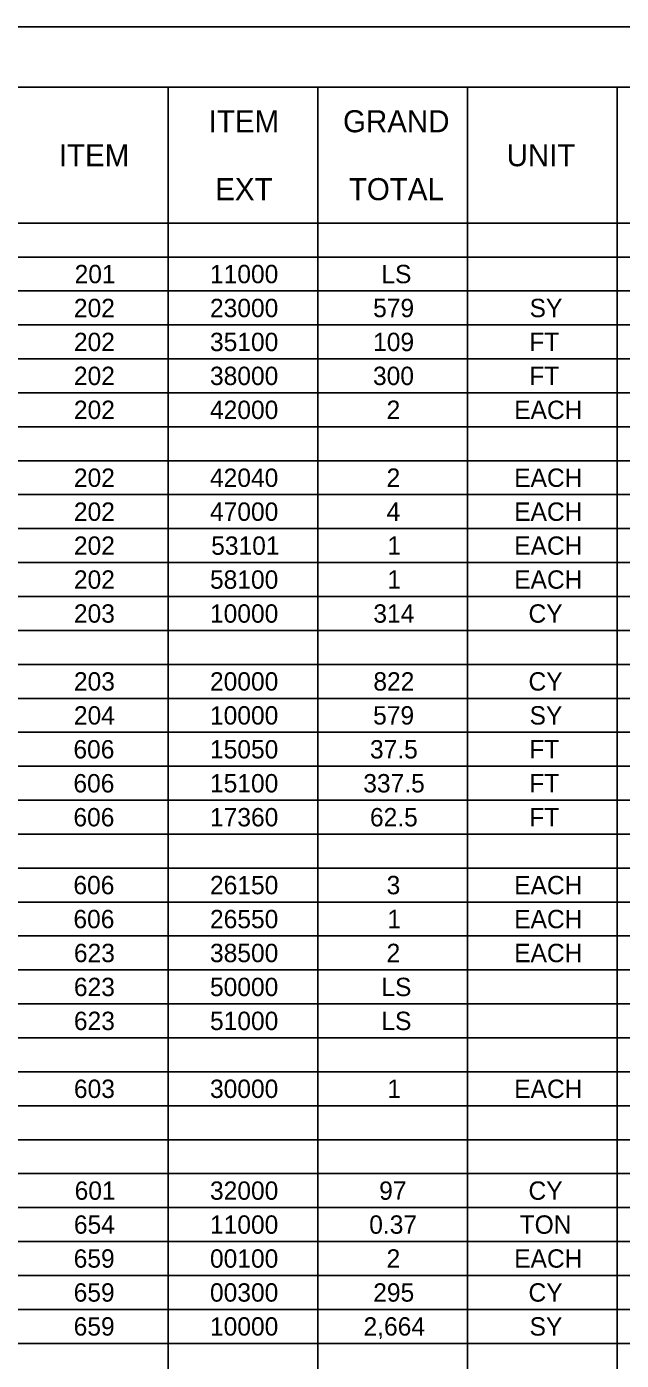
# Model space of a CAD drawing. Extents: x 0 to 34, y 0 to 22.
# Drawn here: x 9.6 to 14.5, y 11 to 22 of the extents above; entities that cross this region are included whole.
import ezdxf

# ---------------------------------------------------------------- set-up
doc = ezdxf.new("R2010")
doc.units = 0
for name, color, linetype in [('Default', 7, 'Continuous'), ('SH_Border', 7, 'Continuous'), ('SH_Cut_Line', 7, 'Continuous')]:
    doc.layers.add(name, color=color, linetype=linetype)

msp = doc.modelspace()

# ---------------------------------------------------------------- linework, layer by layer
at = {"layer": 'Default'}
for p, q in [((1.5, 21.5), (32, 21.5)), ((10.767, 21.5), (10.767, 0.5)), ((12.001, 21.5), (12.001, 0.5)), ((13.236, 21.5), (13.236, 0.5)), ((14.47, 21.5), (14.47, 0.5)), ((1.5, 20.38), (32, 20.38)), ((1.5, 20.1), (32, 20.1)), ((1.5, 19.82), (32, 19.82)), ((1.5, 19.54), (32, 19.54)), ((1.5, 19.26), (32, 19.26)), ((1.5, 18.98), (32, 18.98)), ((1.5, 18.7), (32, 18.7)), ((1.5, 18.42), (32, 18.42)), ((1.5, 18.14), (32, 18.14)), ((1.5, 17.86), (32, 17.86)), ((1.5, 17.58), (32, 17.58)), ((1.5, 17.3), (32, 17.3)), ((1.5, 17.02), (32, 17.02)), ((1.5, 16.74), (32, 16.74)), ((1.5, 16.46), (32, 16.46)), ((1.5, 16.18), (32, 16.18)), ((1.5, 15.9), (32, 15.9)), ((1.5, 15.62), (32, 15.62)), ((1.5, 15.34), (32, 15.34)), ((1.5, 15.06), (32, 15.06)), ((1.5, 14.78), (32, 14.78)), ((1.5, 14.5), (32, 14.5)), ((1.5, 14.22), (32, 14.22)), ((1.5, 13.94), (32, 13.94)), ((1.5, 13.66), (32, 13.66)), ((1.5, 13.38), (32, 13.38)), ((1.5, 13.1), (32, 13.1)), ((1.5, 12.82), (32, 12.82)), ((1.5, 12.54), (32, 12.54)), ((1.5, 12.26), (32, 12.26)), ((1.5, 11.98), (32, 11.98)), ((1.5, 11.7), (32, 11.7)), ((1.5, 11.42), (32, 11.42)), ((1.5, 11.14), (32, 11.14))]:
    msp.add_line(p, q, dxfattribs=at)
at = {"layer": 'SH_Border'}
msp.add_lwpolyline([(1.5, 21.5), (33.5, 21.5), (33.5, 0.5), (1.5, 0.5)], close=True, dxfattribs=at)
at = {"layer": 'SH_Cut_Line'}
msp.add_lwpolyline([(0, 0), (34, 0), (34, 22), (0, 22)], close=True, dxfattribs=at)

# ---------------------------------------------------------------- texts
at = {"layer": 'Default'}
for s, height, p in [('ITEM', 0.1818, (11.101, 21.129)), ('GRAND', 0.1818, (12.209, 21.129)), ('ITEM', 0.1818, (9.866, 20.849)), ('UNIT', 0.1818, (13.558, 20.849)), ('EXT', 0.1818, (11.155, 20.569)), ('TOTAL', 0.1818, (12.257, 20.569)), ('201', 0.1515, (9.996, 19.884)), ('11000', 0.1515, (11.112, 19.884)), ('LS', 0.1515, (12.525, 19.884)), ('202', 0.1515, (9.99, 19.604)), ('23000', 0.1515, (11.112, 19.604)), ('579', 0.1515, (12.457, 19.604)), ('SY', 0.1515, (13.747, 19.604)), ('202', 0.1515, (9.99, 19.324)), ('35100', 0.1515, (11.112, 19.324)), ('109', 0.1515, (12.457, 19.324)), ('FT', 0.1515, (13.744, 19.324)), ('202', 0.1515, (9.99, 19.044)), ('38000', 0.1515, (11.112, 19.044)), ('300', 0.1515, (12.456, 19.044)), ('FT', 0.1515, (13.744, 19.044)), ('202', 0.1515, (9.99, 18.764)), ('42000', 0.1515, (11.112, 18.764)), ('2', 0.152, (12.568, 18.764)), ('EACH', 0.1515, (13.62, 18.764)), ('202', 0.1515, (9.99, 18.204)), ('42040', 0.1515, (11.112, 18.204)), ('2', 0.152, (12.568, 18.204)), ('EACH', 0.1515, (13.62, 18.204)), ('202', 0.1515, (9.99, 17.924)), ('47000', 0.1515, (11.112, 17.924)), ('4', 0.152, (12.568, 17.924)), ('EACH', 0.1515, (13.62, 17.924)), ('202', 0.1515, (9.99, 17.644)), ('53101', 0.1515, (11.122, 17.644)), ('1', 0.152, (12.574, 17.644)), ('EACH', 0.1515, (13.62, 17.644)), ('202', 0.1515, (9.99, 17.364)), ('58100', 0.1515, (11.112, 17.364)), ('1', 0.152, (12.574, 17.364)), ('EACH', 0.1515, (13.62, 17.364)), ('203', 0.1515, (9.99, 17.084)), ('10000', 0.1515, (11.112, 17.084)), ('314', 0.1515, (12.459, 17.084)), ('CY', 0.1515, (13.738, 17.084)), ('203', 0.1515, (9.99, 16.524)), ('20000', 0.1515, (11.112, 16.524)), ('822', 0.1515, (12.459, 16.524)), ('CY', 0.1515, (13.738, 16.524)), ('204', 0.1515, (9.99, 16.244)), ('10000', 0.1515, (11.112, 16.244)), ('579', 0.1515, (12.457, 16.244)), ('SY', 0.1515, (13.747, 16.244)), ('606', 0.1515, (9.986, 15.964)), ('15050', 0.1515, (11.112, 15.964)), ('37.5', 0.1515, (12.431, 15.964)), ('FT', 0.1515, (13.744, 15.964)), ('606', 0.1515, (9.986, 15.684)), ('15100', 0.1515, (11.112, 15.684)), ('337.5', 0.1515, (12.376, 15.684)), ('FT', 0.1515, (13.744, 15.684)), ('606', 0.1515, (9.986, 15.404)), ('17360', 0.1515, (11.112, 15.404)), ('62.5', 0.1515, (12.431, 15.404)), ('FT', 0.1515, (13.744, 15.404)), ('606', 0.1515, (9.986, 14.844)), ('26150', 0.1515, (11.112, 14.844)), ('3', 0.152, (12.568, 14.844)), ('EACH', 0.1515, (13.62, 14.844)), ('606', 0.1515, (9.986, 14.564)), ('26550', 0.1515, (11.112, 14.564)), ('1', 0.152, (12.574, 14.564)), ('EACH', 0.1515, (13.62, 14.564)), ('623', 0.1515, (9.99, 14.284)), ('38500', 0.1515, (11.112, 14.284)), ('2', 0.152, (12.568, 14.284)), ('EACH', 0.1515, (13.62, 14.284)), ('623', 0.1515, (9.99, 14.004)), ('50000', 0.1515, (11.112, 14.004)), ('LS', 0.1515, (12.525, 14.004)), ('623', 0.1515, (9.99, 13.724)), ('51000', 0.1515, (11.112, 13.724)), ('LS', 0.1515, (12.525, 13.724)), ('603', 0.1515, (9.99, 13.164)), ('30000', 0.1515, (11.112, 13.164)), ('1', 0.152, (12.574, 13.164)), ('EACH', 0.1515, (13.62, 13.164)), ('601', 0.1515, (9.996, 12.324)), ('32000', 0.1515, (11.112, 12.324)), ('97', 0.1515, (12.507, 12.324)), ('CY', 0.1515, (13.738, 12.324)), ('654', 0.1515, (9.99, 12.044)), ('11000', 0.1515, (11.112, 12.044)), ('0.37', 0.1515, (12.425, 12.044)), ('TON', 0.1515, (13.665, 12.044)), ('659', 0.1515, (9.988, 11.764)), ('00100', 0.1515, (11.112, 11.764)), ('2', 0.152, (12.568, 11.764)), ('EACH', 0.1515, (13.62, 11.764)), ('659', 0.1515, (9.988, 11.484)), ('00300', 0.1515, (11.112, 11.484)), ('295', 0.1515, (12.458, 11.484)), ('CY', 0.1515, (13.738, 11.484)), ('659', 0.1515, (9.988, 11.204)), ('10000', 0.1515, (11.112, 11.204)), ('2,664', 0.1515, (12.378, 11.204)), ('SY', 0.1515, (13.747, 11.204))]:
    msp.add_text(s, height=height, dxfattribs=at).set_placement(p)

doc.saveas('drawing.dxf')
